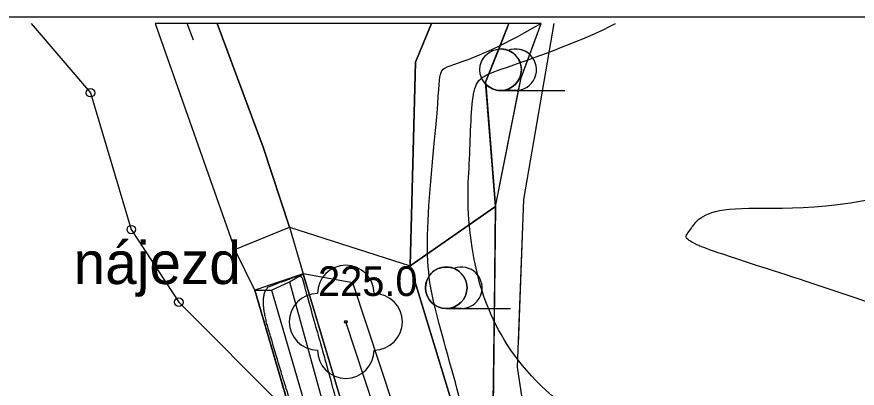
# Model space of a CAD drawing. Extents: x -495905 to -478420, y -1113297 to -1107716.
# Drawn here: x -483993.1 to -483933.7, y -1112105.2 to -1112078.9 of the extents above; entities that cross this region are included whole.
import ezdxf

# ---------------------------------------------------------------- set-up
doc = ezdxf.new("R2010")
doc.units = 0
for name, color, linetype in [('01_OBVOD PÚ', 7, 'Continuous'), ('07_SDĚLOVACÍ_P', 7, 'Continuous'), ('2D_VRSTEVNICE', 7, 'Continuous'), ('Implicitní', 7, 'Continuous'), ('ttp', 7, 'Continuous'), ('VODNÍ PLOCHY', 7, 'Continuous'), ('VYRAZNE_VRST', 7, 'Continuous'), ('zamereni', 7, 'Continuous'), ('ZELEN MIMO LES', 7, 'Continuous')]:
    doc.layers.add(name, color=color, linetype=linetype)

msp = doc.modelspace()

# ---------------------------------------------------------------- linework, layer by layer
at = {"layer": '01_OBVOD PÚ'}
for p, q in [((-483992.041, -1112079.43), (-483987.85, -1112084.32)), ((-483987.85, -1112084.32), (-483984.97, -1112094)), ((-483984.97, -1112094), (-483981.61, -1112099.13)), ((-483981.61, -1112099.13), (-483968.69, -1112112.08))]:
    msp.add_line(p, q, dxfattribs=at)
at = {"layer": '07_SDĚLOVACÍ_P'}
for points in [[(-483946.86, -1112138.22), (-483945.9, -1112135.67), (-483947.21, -1112132.78), (-483951.41, -1112123.45), (-483956.47, -1112111.69), (-483957.67, -1112103.73), (-483957.23, -1112091.87), (-483955.077, -1112079.43)], [(-483946.86, -1112138.22), (-483945.9, -1112135.67), (-483947.21, -1112132.78), (-483951.41, -1112123.45), (-483956.47, -1112111.69), (-483957.67, -1112103.73), (-483957.23, -1112091.87), (-483955.077, -1112079.43)], [(-483957.609, -1112102.098), (-483957.23, -1112091.87), (-483955.077, -1112079.43)]]:
    msp.add_lwpolyline(points, dxfattribs=at)
at = {"layer": '2D_VRSTEVNICE'}
for points in [[(-483954.893, -1112123.045), (-483959.779, -1112113.051), (-483960.83, -1112109.275), (-483963.326, -1112100.302), (-483964.43, -1112095.989), (-483963.225, -1112085.155), (-483963.229, -1112082.632), (-483962.596, -1112082.498), (-483959.177, -1112081.25), (-483956.034, -1112079.43)], [(-483954.813, -1112106.103), (-483959.342, -1112102.39), (-483961.503, -1112093.95), (-483960.975, -1112089.203), (-483960.985, -1112083.27), (-483959.497, -1112082.954), (-483952.98, -1112080.577), (-483950.742, -1112079.43)], [(-483928.35, -1112101.107), (-483929.03, -1112100.289), (-483944.624, -1112095.332), (-483944.97, -1112095.064), (-483945.983, -1112094.588), (-483945.502, -1112094.131), (-483944.12, -1112091.92), (-483931.713, -1112093.313), (-483910.147, -1112082.315), (-483908.083, -1112082.432), (-483906.722, -1112079.43)]]:
    msp.add_open_spline(points, degree=3, dxfattribs=at)
at = {"layer": 'Implicitní'}
msp.add_lwpolyline([(-483828.6, -1112213.4), (-484020.92, -1112213.4), (-484020.92, -1112078.95), (-483828.6, -1112078.95)], close=True, dxfattribs=at)
at = {"layer": 'ttp'}
for points in [[(-483963.759, -1112079.43), (-483978.908, -1112079.43)], [(-483978.908, -1112079.43), (-483975.65, -1112088.16), (-483973.79, -1112093.83), (-483965.25, -1112096.56), (-483964.89, -1112082.16), (-483963.759, -1112079.43)]]:
    msp.add_lwpolyline(points, dxfattribs=at)
at = {"layer": 'VODNÍ PLOCHY'}
for points in [[(-483983.275, -1112079.43), (-483977.66, -1112095.41)], [(-483978.908, -1112079.43), (-483983.275, -1112079.43)], [(-483977.66, -1112095.41), (-483973.79, -1112093.83), (-483975.65, -1112088.16), (-483978.908, -1112079.43)], [(-483976.23, -1112098.28), (-483967.06, -1112129.71), (-483964.08, -1112128.29), (-483963.97, -1112126.74), (-483972.83, -1112097.12), (-483976.23, -1112098.28)]]:
    msp.add_lwpolyline(points, dxfattribs=at)
at = {"layer": 'VYRAZNE_VRST'}
for points in [[(-483971.584, -1112113.402), (-483971.876, -1112112.469), (-483973.853, -1112105.762), (-483974.218, -1112104.589), (-483974.476, -1112103.757), (-483976.088, -1112098.281), (-483973.975, -1112097.569), (-483973.79, -1112097.478), (-483972.952, -1112097.194), (-483972.803, -1112097.713), (-483972.794, -1112097.749), (-483972.55, -1112098.694)], [(-483972.55, -1112098.694), (-483971, -1112104.16), (-483970.596, -1112105.744), (-483968.308, -1112113.88), (-483967.845, -1112115.736), (-483967.712, -1112116.211), (-483967.665, -1112116.398)]]:
    msp.add_open_spline(points, degree=2, dxfattribs=at)
at = {"layer": 'zamereni'}
for p, q in [((-483983.275, -1112079.43), (-483977.66, -1112095.41)), ((-483980.572, -1112080.601), (-483981.009, -1112079.43)), ((-483975.65, -1112088.16), (-483978.908, -1112079.43)), ((-483964.89, -1112082.16), (-483963.759, -1112079.43)), ((-483958.281, -1112079.43), (-483959.93, -1112083.57)), ((-483957.42, -1112083.26), (-483955.992, -1112079.43)), ((-483965.25, -1112096.56), (-483964.89, -1112082.16)), ((-483959.93, -1112083.57), (-483959.22, -1112092.36)), ((-483959.22, -1112092.36), (-483957.42, -1112083.26)), ((-483958.87, -1112084.16), (-483954.336, -1112084.16)), ((-483973.79, -1112093.83), (-483975.65, -1112088.16)), ((-483959.22, -1112092.36), (-483965.25, -1112096.56)), ((-483959.22, -1112092.36), (-483959.41, -1112107.92)), ((-483977.66, -1112095.41), (-483973.79, -1112093.83)), ((-483973.79, -1112093.83), (-483972.83, -1112097.12)), ((-483973.79, -1112093.83), (-483965.25, -1112096.56)), ((-483976.23, -1112098.28), (-483977.66, -1112095.41)), ((-483956.32, -1112125.94), (-483965.25, -1112096.56)), ((-483972.83, -1112097.12), (-483976.23, -1112098.28)), ((-483973.79, -1112097.7), (-483972.83, -1112097.12)), ((-483972.83, -1112097.12), (-483963.97, -1112126.74)), ((-483969.32, -1112097.76), (-483972.83, -1112097.12)), ((-483975.07, -1112098.29), (-483973.79, -1112097.7)), ((-483973.79, -1112097.7), (-483968.55, -1112116.64)), ((-483960.58, -1112124.17), (-483969.32, -1112097.76)), ((-483967.06, -1112129.71), (-483976.23, -1112098.28)), ((-483976.23, -1112098.28), (-483975.07, -1112098.29)), ((-483975.07, -1112098.29), (-483969.66, -1112116.64)), ((-483962.71, -1112099.58), (-483958.176, -1112099.58)), ((-483962.46, -1112122.65), (-483969.81, -1112100.52)), ((-483969.81, -1112100.52), (-483969.81, -1112100.52))]:
    msp.add_line(p, q, dxfattribs=at)
for centre, radius in [((-483958.869, -1112082.693), 1.467), ((-483987.85, -1112084.32), 0.3), ((-483984.97, -1112094), 0.3), ((-483962.709, -1112098.113), 1.467), ((-483981.61, -1112099.13), 0.3), ((-483969.81, -1112100.52), 0.1)]:
    msp.add_circle(centre, radius, dxfattribs=at)
for centre, radius, start, end in [((-483957.803, -1112082.693), 1.467, 270, 111.324), ((-483969.81, -1112098.52), 2, 0, 180), ((-483961.643, -1112098.113), 1.467, 270, 111.324), ((-483971.81, -1112100.52), 2, 90, 270), ((-483967.81, -1112100.52), 2, 270, 90), ((-483969.81, -1112102.52), 2, 180, 0)]:
    msp.add_arc(centre, radius, start, end, dxfattribs=at)
at = {"layer": 'ZELEN MIMO LES'}
for points in [[(-483963.759, -1112079.43), (-483964.89, -1112082.16), (-483965.25, -1112096.56), (-483959.22, -1112092.36), (-483959.93, -1112083.57), (-483958.281, -1112079.43)], [(-483958.281, -1112079.43), (-483963.759, -1112079.43)], [(-483958.281, -1112079.43), (-483958.999, -1112081.232)], [(-483955.992, -1112079.43), (-483958.281, -1112079.43)], [(-483956.807, -1112081.616), (-483955.992, -1112079.43)], [(-483958.999, -1112081.232), (-483959.93, -1112083.57), (-483959.918, -1112083.719)], [(-483958.336, -1112081.327), (-483958.336, -1112081.327)], [(-483957.595, -1112084.145), (-483957.42, -1112083.26), (-483956.807, -1112081.616)], [(-483959.918, -1112083.719), (-483959.22, -1112092.36), (-483957.598, -1112084.16), (-483957.803, -1112084.16), (-483958.87, -1112084.16)], [(-483958.87, -1112084.16), (-483958.869, -1112084.16)], [(-483958.869, -1112084.16), (-483957.803, -1112084.16)], [(-483959.308, -1112099.58), (-483959.22, -1112092.36), (-483965.25, -1112096.56), (-483956.32, -1112125.94), (-483953.79, -1112124.99), (-483959.41, -1112107.92), (-483959.308, -1112099.58)], [(-483961.643, -1112099.58), (-483962.71, -1112099.58)], [(-483962.709, -1112099.58), (-483961.643, -1112099.58), (-483961.642, -1112099.58)]]:
    msp.add_lwpolyline(points, dxfattribs=at)
for centre, start, end in [((-483958.869, -1112082.693), 68.67631, 95.07146), ((-483958.869, -1112082.693), 68.67654, 95.07146), ((-483957.803, -1112082.693), 47.24712, 111.32369), ((-483957.803, -1112082.693), 47.24712, 111.32369), ((-483958.869, -1112082.693), 0, 68.67631), ((-483957.803, -1112082.693), 111.32369, 111.324), ((-483958.869, -1112082.693), 0, 68.67631), ((-483958.869, -1112082.693), 270.02577, 0), ((-483958.869, -1112082.693), 270.02577, 0), ((-483958.869, -1112082.693), 224.36104, 269.97422), ((-483958.869, -1112082.693), 224.36104, 269.97422), ((-483957.803, -1112082.693), 270, 278.13358), ((-483962.709, -1112098.113), 68.67654, 180), ((-483962.709, -1112098.113), 68.67654, 180), ((-483961.643, -1112098.113), 270, 111.324), ((-483961.643, -1112098.113), 270.02254, 111.32369), ((-483962.709, -1112098.113), 0, 68.67631), ((-483961.643, -1112098.113), 111.32369, 111.324), ((-483962.709, -1112098.113), 0, 68.67631), ((-483962.709, -1112098.113), 180, 269.97422), ((-483962.709, -1112098.113), 180, 0), ((-483962.709, -1112098.113), 270.02577, 0)]:
    msp.add_arc(centre, 1.467, start, end, dxfattribs=at)

# ---------------------------------------------------------------- texts
at = {"layer": 'VYRAZNE_VRST'}
msp.add_text(' 225.0', height=2.1, dxfattribs=at).set_placement((-483972.55, -1112098.694))
msp.add_text(' 225.0', height=2.1, dxfattribs=at).set_placement((-483972.55, -1112098.694))
at = {"layer": 'zamereni'}
msp.add_text('nájezd', height=3, dxfattribs=at).set_placement((-483989.044, -1112097.85))

doc.saveas('drawing.dxf')
